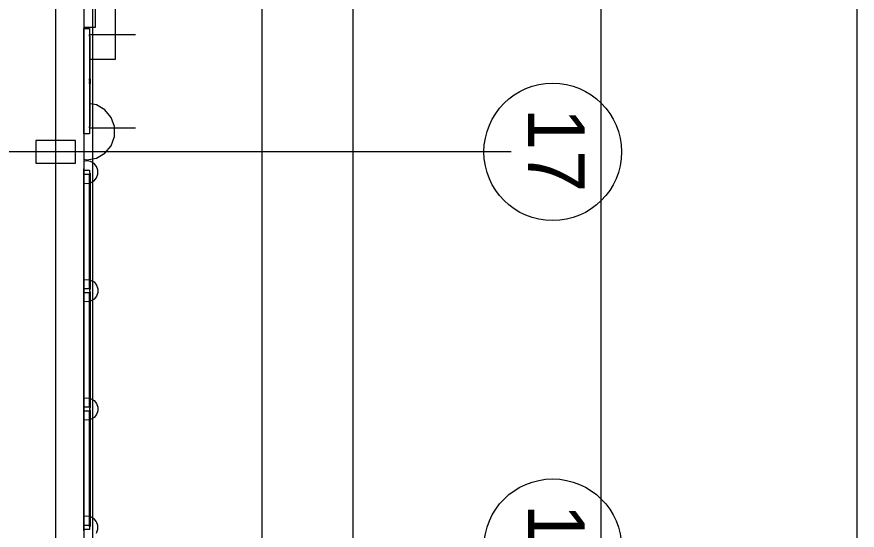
# Model space of a CAD drawing. Extents: x -264165 to -263575, y -1242333 to -1242036.
# Drawn here: x -263796.23 to -263781.36, y -1242195.57 to -1242186.49 of the extents above; entities that cross this region are included whole.
import ezdxf

# ---------------------------------------------------------------- set-up
doc = ezdxf.new("R2010")
doc.units = 0
doc.layers.add('KFA_HESCON_OSI_STAVBY', color=7, linetype='Continuous')
doc.layers.add('KFA_SITUACIA_DRS_VYTYCOVAK_SEDA', color=7, linetype='Continuous')

msp = doc.modelspace()

# ---------------------------------------------------------------- linework, layer by layer
at = {"layer": 'KFA_HESCON_OSI_STAVBY'}
for p, q in [((-263795.543, -1242080.447), (-263795.543, -1242248.737)), ((-263787.486, -1242188.882), (-263921.823, -1242188.882)), ((-263787.486, -1242188.882), (-263787.486, -1242188.882))]:
    msp.add_line(p, q, dxfattribs=at)
for centre in [(-263786.751, -1242188.882), (-263786.751, -1242195.882)]:
    msp.add_circle(centre, 1.216, dxfattribs=at)
at = {"layer": 'KFA_SITUACIA_DRS_VYTYCOVAK_SEDA'}
for p, q in [((-263781.364, -1242208.936), (-263781.371, -1242084.903)), ((-263781.364, -1242208.936), (-263781.371, -1242084.903)), ((-263785.893, -1242228.625), (-263785.893, -1242090.308)), ((-263791.893, -1242228.625), (-263791.893, -1242100.14)), ((-263790.279, -1242228.625), (-263790.279, -1242100.14)), ((-263794.893, -1242101.382), (-263794.893, -1242227.382)), ((-263795.043, -1242181.882), (-263795.043, -1242188.882)), ((-263795.043, -1242181.882), (-263795.043, -1242188.882)), ((-263794.482, -1242187.242), (-263794.482, -1242183.522)), ((-263794.482, -1242187.242), (-263794.482, -1242183.522)), ((-263794.847, -1242184.082), (-263794.847, -1242186.682)), ((-263794.847, -1242184.082), (-263794.847, -1242186.682)), ((-263795.043, -1242186.682), (-263795.043, -1242186.702)), ((-263795.043, -1242186.682), (-263795.043, -1242186.702)), ((-263794.847, -1242186.682), (-263795.043, -1242186.682)), ((-263794.847, -1242186.682), (-263795.043, -1242186.682)), ((-263795.043, -1242188.562), (-263795.043, -1242186.702)), ((-263795.043, -1242188.562), (-263795.043, -1242186.702)), ((-263795.043, -1242186.702), (-263794.943, -1242186.702)), ((-263795.043, -1242186.702), (-263794.943, -1242186.702)), ((-263794.943, -1242186.702), (-263794.943, -1242188.562)), ((-263794.943, -1242186.702), (-263794.943, -1242188.562)), ((-263794.943, -1242186.807), (-263794.128, -1242186.807)), ((-263794.943, -1242186.807), (-263794.128, -1242186.807)), ((-263794.943, -1242186.833), (-263794.943, -1242186.807)), ((-263794.943, -1242186.833), (-263794.943, -1242186.807)), ((-263794.943, -1242186.833), (-263794.933, -1242186.833)), ((-263794.943, -1242186.833), (-263794.933, -1242186.833)), ((-263794.933, -1242187.592), (-263794.933, -1242186.833)), ((-263794.933, -1242187.592), (-263794.933, -1242186.833)), ((-263794.933, -1242187.242), (-263794.482, -1242187.242)), ((-263794.933, -1242187.242), (-263794.482, -1242187.242)), ((-263794.943, -1242187.592), (-263794.933, -1242187.592)), ((-263794.943, -1242187.592), (-263794.933, -1242187.592)), ((-263794.943, -1242187.622), (-263794.943, -1242187.592)), ((-263794.943, -1242187.622), (-263794.943, -1242187.592)), ((-263794.943, -1242187.592), (-263794.933, -1242187.592)), ((-263794.943, -1242187.592), (-263794.933, -1242187.592)), ((-263794.943, -1242187.673), (-263794.943, -1242187.642)), ((-263794.943, -1242187.673), (-263794.943, -1242187.642)), ((-263794.933, -1242187.672), (-263794.943, -1242187.672)), ((-263794.933, -1242187.672), (-263794.943, -1242187.672)), ((-263794.933, -1242187.673), (-263794.943, -1242187.673)), ((-263794.933, -1242187.673), (-263794.943, -1242187.673)), ((-263794.933, -1242187.592), (-263794.933, -1242187.672)), ((-263794.933, -1242187.592), (-263794.933, -1242187.672)), ((-263794.933, -1242188.432), (-263794.933, -1242187.673)), ((-263794.933, -1242188.432), (-263794.933, -1242187.673)), ((-263794.822, -1242188.052), (-263794.933, -1242188.033)), ((-263794.822, -1242188.052), (-263794.933, -1242188.033)), ((-263794.671, -1242188.139), (-263794.822, -1242188.052)), ((-263794.671, -1242188.139), (-263794.822, -1242188.052)), ((-263794.56, -1242188.272), (-263794.671, -1242188.139)), ((-263794.56, -1242188.272), (-263794.671, -1242188.139)), ((-263794.5, -1242188.435), (-263794.56, -1242188.272)), ((-263794.5, -1242188.435), (-263794.56, -1242188.272)), ((-263794.943, -1242188.457), (-263794.943, -1242188.432)), ((-263794.943, -1242188.457), (-263794.943, -1242188.432)), ((-263794.933, -1242188.432), (-263794.943, -1242188.432)), ((-263794.933, -1242188.432), (-263794.943, -1242188.432)), ((-263794.943, -1242188.457), (-263794.128, -1242188.457)), ((-263794.943, -1242188.457), (-263794.128, -1242188.457)), ((-263794.5, -1242188.609), (-263794.5, -1242188.435)), ((-263794.5, -1242188.609), (-263794.5, -1242188.435)), ((-263795.043, -1242188.562), (-263795.043, -1242188.582)), ((-263795.043, -1242188.562), (-263795.043, -1242188.582)), ((-263794.943, -1242188.562), (-263795.043, -1242188.562)), ((-263794.943, -1242188.562), (-263795.043, -1242188.562)), ((-263795.043, -1242188.582), (-263795.043, -1242189.182)), ((-263795.043, -1242188.582), (-263795.043, -1242189.182)), ((-263795.193, -1242188.682), (-263795.893, -1242188.682)), ((-263795.193, -1242188.682), (-263795.893, -1242188.682)), ((-263795.893, -1242188.682), (-263795.893, -1242188.882)), ((-263795.893, -1242188.682), (-263795.893, -1242188.882)), ((-263795.193, -1242188.882), (-263795.193, -1242188.682)), ((-263795.193, -1242188.882), (-263795.193, -1242188.682)), ((-263795.193, -1242188.882), (-263795.193, -1242188.682)), ((-263795.193, -1242188.882), (-263795.193, -1242188.682)), ((-263794.56, -1242188.772), (-263794.5, -1242188.609)), ((-263794.56, -1242188.772), (-263794.5, -1242188.609)), ((-263795.893, -1242188.882), (-263795.893, -1242189.082)), ((-263795.893, -1242188.882), (-263795.893, -1242189.082)), ((-263795.193, -1242189.082), (-263795.193, -1242188.882)), ((-263795.193, -1242189.082), (-263795.193, -1242188.882)), ((-263795.193, -1242189.082), (-263795.193, -1242188.882)), ((-263795.193, -1242189.082), (-263795.193, -1242188.882)), ((-263795.043, -1242188.882), (-263795.043, -1242195.882)), ((-263795.043, -1242188.882), (-263795.043, -1242195.882)), ((-263794.671, -1242188.905), (-263794.56, -1242188.772)), ((-263794.671, -1242188.905), (-263794.56, -1242188.772)), ((-263795.043, -1242189.013), (-263794.993, -1242189.022)), ((-263795.043, -1242189.013), (-263794.993, -1242189.022)), ((-263794.993, -1242189.042), (-263795.043, -1242189.051)), ((-263794.993, -1242189.042), (-263795.043, -1242189.051)), ((-263794.993, -1242189.022), (-263794.822, -1242188.992)), ((-263794.993, -1242189.022), (-263794.822, -1242188.992)), ((-263794.924, -1242189.054), (-263794.993, -1242189.042)), ((-263794.924, -1242189.054), (-263794.993, -1242189.042)), ((-263794.822, -1242188.992), (-263794.671, -1242188.905)), ((-263794.822, -1242188.992), (-263794.671, -1242188.905)), ((-263795.893, -1242189.082), (-263795.193, -1242189.082)), ((-263795.893, -1242189.082), (-263795.193, -1242189.082)), ((-263795.043, -1242189.202), (-263795.043, -1242189.182)), ((-263795.043, -1242189.202), (-263795.043, -1242189.182)), ((-263794.864, -1242189.089), (-263794.924, -1242189.054)), ((-263794.864, -1242189.089), (-263794.924, -1242189.054)), ((-263794.82, -1242189.142), (-263794.864, -1242189.089)), ((-263794.82, -1242189.142), (-263794.864, -1242189.089)), ((-263794.796, -1242189.207), (-263794.82, -1242189.142)), ((-263794.796, -1242189.207), (-263794.82, -1242189.142)), ((-263795.043, -1242189.282), (-263795.043, -1242189.202)), ((-263795.043, -1242189.282), (-263795.043, -1242189.202)), ((-263795.043, -1242189.202), (-263794.943, -1242189.202)), ((-263795.043, -1242189.202), (-263794.943, -1242189.202)), ((-263795.043, -1242191.296), (-263795.043, -1242189.282)), ((-263795.043, -1242191.296), (-263795.043, -1242189.282)), ((-263794.943, -1242189.282), (-263795.043, -1242189.282)), ((-263794.943, -1242189.282), (-263795.043, -1242189.282)), ((-263794.943, -1242189.202), (-263794.943, -1242189.259)), ((-263794.943, -1242189.202), (-263794.943, -1242189.259)), ((-263794.933, -1242189.259), (-263794.943, -1242189.259)), ((-263794.933, -1242189.259), (-263794.943, -1242189.259)), ((-263794.943, -1242191.296), (-263794.943, -1242189.282)), ((-263794.943, -1242191.296), (-263794.943, -1242189.282)), ((-263794.933, -1242189.259), (-263794.933, -1242191.318)), ((-263794.933, -1242189.259), (-263794.933, -1242191.318)), ((-263794.864, -1242189.395), (-263794.82, -1242189.342)), ((-263794.864, -1242189.395), (-263794.82, -1242189.342)), ((-263794.82, -1242189.342), (-263794.796, -1242189.277)), ((-263794.82, -1242189.342), (-263794.796, -1242189.277)), ((-263794.796, -1242189.277), (-263794.796, -1242189.207)), ((-263794.796, -1242189.277), (-263794.796, -1242189.207)), ((-263795.043, -1242189.433), (-263794.993, -1242189.442)), ((-263795.043, -1242189.433), (-263794.993, -1242189.442)), ((-263794.993, -1242189.442), (-263794.943, -1242189.433)), ((-263794.993, -1242189.442), (-263794.943, -1242189.433)), ((-263794.933, -1242189.432), (-263794.924, -1242189.43)), ((-263794.933, -1242189.432), (-263794.924, -1242189.43)), ((-263794.924, -1242189.43), (-263794.864, -1242189.395)), ((-263794.924, -1242189.43), (-263794.864, -1242189.395)), ((-263795.043, -1242191.144), (-263794.993, -1242191.136)), ((-263795.043, -1242191.144), (-263794.993, -1242191.136)), ((-263794.993, -1242191.136), (-263794.943, -1242191.144)), ((-263794.993, -1242191.136), (-263794.943, -1242191.144)), ((-263794.933, -1242191.146), (-263794.924, -1242191.148)), ((-263794.933, -1242191.146), (-263794.924, -1242191.148)), ((-263794.924, -1242191.148), (-263794.864, -1242191.182)), ((-263794.924, -1242191.148), (-263794.864, -1242191.182)), ((-263794.864, -1242191.182), (-263794.82, -1242191.236)), ((-263794.864, -1242191.182), (-263794.82, -1242191.236)), ((-263794.82, -1242191.236), (-263794.796, -1242191.301)), ((-263794.82, -1242191.236), (-263794.796, -1242191.301)), ((-263795.043, -1242191.376), (-263795.043, -1242191.296)), ((-263795.043, -1242191.376), (-263795.043, -1242191.296)), ((-263795.043, -1242191.296), (-263794.943, -1242191.296)), ((-263795.043, -1242191.296), (-263794.943, -1242191.296)), ((-263795.043, -1242193.389), (-263795.043, -1242191.376)), ((-263795.043, -1242193.389), (-263795.043, -1242191.376)), ((-263794.943, -1242191.376), (-263795.043, -1242191.376)), ((-263794.943, -1242191.376), (-263795.043, -1242191.376)), ((-263794.933, -1242191.318), (-263794.943, -1242191.318)), ((-263794.933, -1242191.318), (-263794.943, -1242191.318)), ((-263794.943, -1242191.318), (-263794.943, -1242191.353)), ((-263794.943, -1242191.318), (-263794.943, -1242191.353)), ((-263794.933, -1242191.353), (-263794.943, -1242191.353)), ((-263794.933, -1242191.353), (-263794.943, -1242191.353)), ((-263794.943, -1242193.389), (-263794.943, -1242191.376)), ((-263794.943, -1242193.389), (-263794.943, -1242191.376)), ((-263794.933, -1242191.353), (-263794.933, -1242193.412)), ((-263794.933, -1242191.353), (-263794.933, -1242193.412)), ((-263794.796, -1242191.37), (-263794.82, -1242191.436)), ((-263794.796, -1242191.37), (-263794.82, -1242191.436)), ((-263794.796, -1242191.301), (-263794.796, -1242191.37)), ((-263794.796, -1242191.301), (-263794.796, -1242191.37)), ((-263794.993, -1242191.536), (-263795.043, -1242191.527)), ((-263794.993, -1242191.536), (-263795.043, -1242191.527)), ((-263794.943, -1242191.527), (-263794.993, -1242191.536)), ((-263794.943, -1242191.527), (-263794.993, -1242191.536)), ((-263794.924, -1242191.523), (-263794.933, -1242191.525)), ((-263794.924, -1242191.523), (-263794.933, -1242191.525)), ((-263794.864, -1242191.489), (-263794.924, -1242191.523)), ((-263794.864, -1242191.489), (-263794.924, -1242191.523)), ((-263794.82, -1242191.436), (-263794.864, -1242191.489)), ((-263794.82, -1242191.436), (-263794.864, -1242191.489)), ((-263795.043, -1242193.238), (-263794.993, -1242193.229)), ((-263795.043, -1242193.238), (-263794.993, -1242193.229)), ((-263794.993, -1242193.229), (-263794.943, -1242193.238)), ((-263794.993, -1242193.229), (-263794.943, -1242193.238)), ((-263794.933, -1242193.239), (-263794.924, -1242193.241)), ((-263794.933, -1242193.239), (-263794.924, -1242193.241)), ((-263794.924, -1242193.241), (-263794.864, -1242193.276)), ((-263794.924, -1242193.241), (-263794.864, -1242193.276)), ((-263794.864, -1242193.276), (-263794.82, -1242193.329)), ((-263794.864, -1242193.276), (-263794.82, -1242193.329)), ((-263794.82, -1242193.329), (-263794.796, -1242193.394)), ((-263794.82, -1242193.329), (-263794.796, -1242193.394)), ((-263795.043, -1242193.469), (-263795.043, -1242193.389)), ((-263795.043, -1242193.469), (-263795.043, -1242193.389)), ((-263795.043, -1242193.389), (-263794.943, -1242193.389)), ((-263795.043, -1242193.389), (-263794.943, -1242193.389)), ((-263795.043, -1242195.482), (-263795.043, -1242193.469)), ((-263795.043, -1242195.482), (-263795.043, -1242193.469)), ((-263794.943, -1242193.469), (-263795.043, -1242193.469)), ((-263794.943, -1242193.469), (-263795.043, -1242193.469)), ((-263794.933, -1242193.412), (-263794.943, -1242193.412)), ((-263794.933, -1242193.412), (-263794.943, -1242193.412)), ((-263794.943, -1242193.412), (-263794.943, -1242193.446)), ((-263794.943, -1242193.412), (-263794.943, -1242193.446)), ((-263794.933, -1242193.446), (-263794.943, -1242193.446)), ((-263794.933, -1242193.446), (-263794.943, -1242193.446)), ((-263794.943, -1242195.505), (-263794.943, -1242193.469)), ((-263794.943, -1242195.505), (-263794.943, -1242193.469)), ((-263794.933, -1242193.446), (-263794.933, -1242195.505)), ((-263794.933, -1242193.446), (-263794.933, -1242195.505)), ((-263794.796, -1242193.464), (-263794.82, -1242193.529)), ((-263794.796, -1242193.464), (-263794.82, -1242193.529)), ((-263794.796, -1242193.394), (-263794.796, -1242193.464)), ((-263794.796, -1242193.394), (-263794.796, -1242193.464)), ((-263794.993, -1242193.629), (-263795.043, -1242193.62)), ((-263794.993, -1242193.629), (-263795.043, -1242193.62)), ((-263794.943, -1242193.62), (-263794.993, -1242193.629)), ((-263794.943, -1242193.62), (-263794.993, -1242193.629)), ((-263794.924, -1242193.617), (-263794.933, -1242193.618)), ((-263794.924, -1242193.617), (-263794.933, -1242193.618)), ((-263794.864, -1242193.582), (-263794.924, -1242193.617)), ((-263794.864, -1242193.582), (-263794.924, -1242193.617)), ((-263794.82, -1242193.529), (-263794.864, -1242193.582)), ((-263794.82, -1242193.529), (-263794.864, -1242193.582)), ((-263794.993, -1242195.322), (-263795.043, -1242195.331)), ((-263794.993, -1242195.322), (-263795.043, -1242195.331)), ((-263794.943, -1242195.331), (-263794.993, -1242195.322)), ((-263794.943, -1242195.331), (-263794.993, -1242195.322)), ((-263794.924, -1242195.334), (-263794.933, -1242195.333)), ((-263794.924, -1242195.334), (-263794.933, -1242195.333)), ((-263794.864, -1242195.369), (-263794.924, -1242195.334)), ((-263794.864, -1242195.369), (-263794.924, -1242195.334)), ((-263794.82, -1242195.422), (-263794.864, -1242195.369)), ((-263794.82, -1242195.422), (-263794.864, -1242195.369)), ((-263794.796, -1242195.487), (-263794.82, -1242195.422)), ((-263794.796, -1242195.487), (-263794.82, -1242195.422)), ((-263795.043, -1242195.562), (-263795.043, -1242195.482)), ((-263795.043, -1242195.562), (-263795.043, -1242195.482)), ((-263795.043, -1242195.482), (-263794.943, -1242195.482)), ((-263795.043, -1242195.482), (-263794.943, -1242195.482)), ((-263795.043, -1242195.582), (-263795.043, -1242195.562)), ((-263795.043, -1242195.582), (-263795.043, -1242195.562)), ((-263794.943, -1242195.562), (-263795.043, -1242195.562)), ((-263794.943, -1242195.562), (-263795.043, -1242195.562)), ((-263794.943, -1242195.482), (-263794.943, -1242195.562)), ((-263794.943, -1242195.482), (-263794.943, -1242195.562)), ((-263794.933, -1242195.505), (-263794.943, -1242195.505)), ((-263794.933, -1242195.505), (-263794.943, -1242195.505)), ((-263794.82, -1242195.622), (-263794.796, -1242195.557)), ((-263794.82, -1242195.622), (-263794.796, -1242195.557)), ((-263794.796, -1242195.557), (-263794.796, -1242195.487)), ((-263794.796, -1242195.557), (-263794.796, -1242195.487))]:
    msp.add_line(p, q, dxfattribs=at)

# ---------------------------------------------------------------- texts
at = {"layer": 'KFA_HESCON_OSI_STAVBY'}
for s, p in [('17', (-263787.186, -1242188.105)), ('18', (-263787.186, -1242195.105))]:
    msp.add_text(s, height=1, rotation=270, dxfattribs=at).set_placement(p)

doc.saveas('drawing.dxf')
